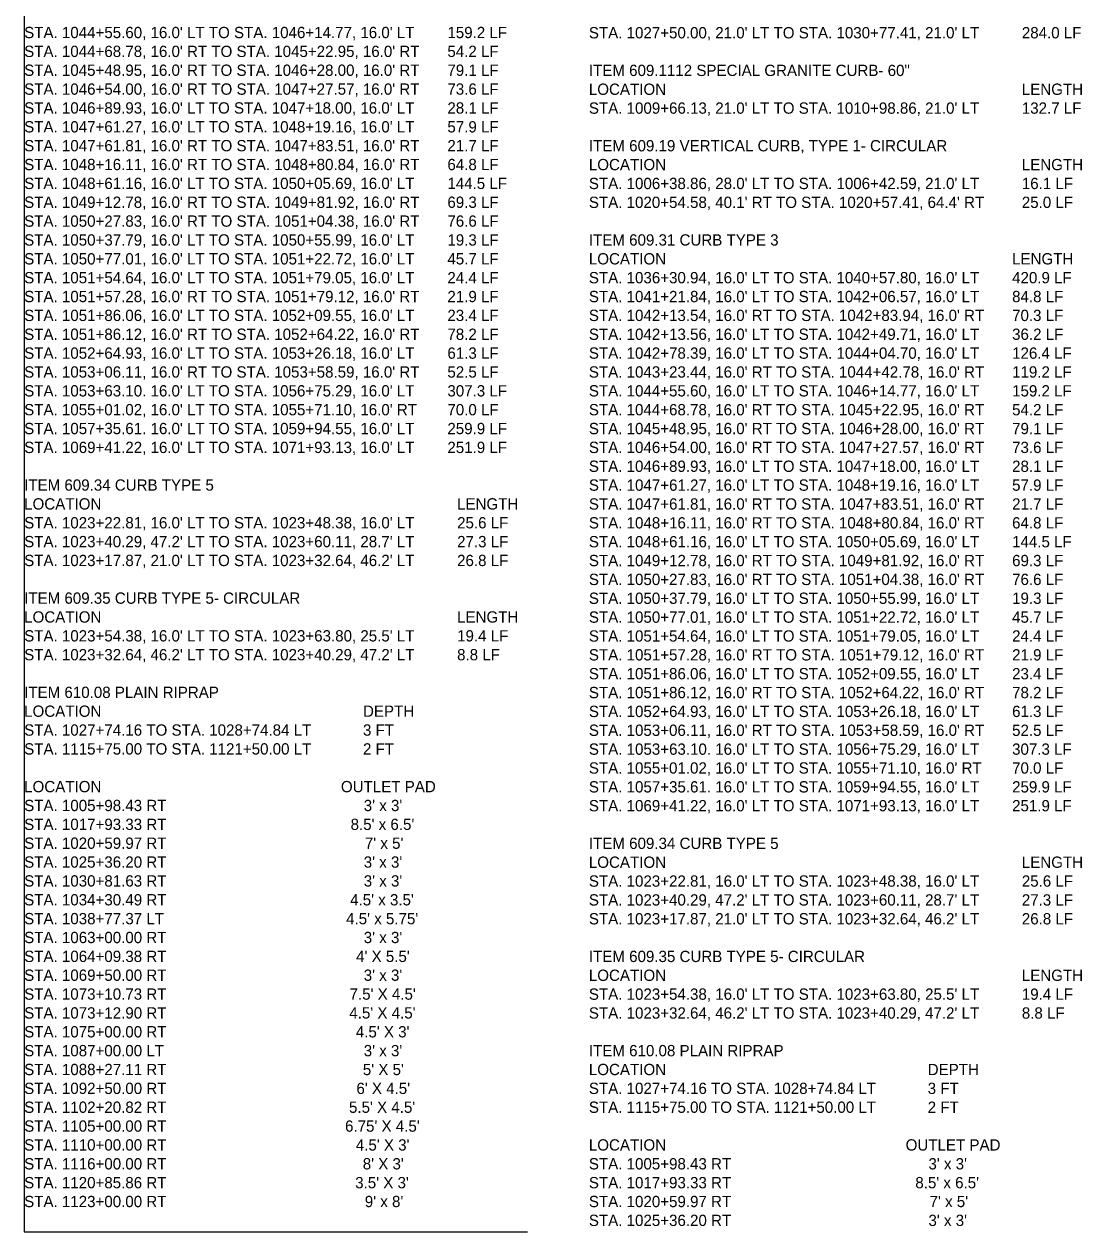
# Model space of a CAD drawing. Extents: x -831 to 3331, y -1004 to 250.
# Drawn here: x -306.8 to -25.8, y -719.8 to -399 of the extents above; entities that cross this region are included whole.
import ezdxf

# ---------------------------------------------------------------- set-up
doc = ezdxf.new("R2010")
doc.units = 0
doc.layers.add('Default', color=7, linetype='Continuous')

msp = doc.modelspace()

# ---------------------------------------------------------------- linework, layer by layer
at = {"layer": 'Default'}
msp.add_line((-306.76, -204.41), (-306.76, -715.41), dxfattribs=at)
msp.add_lwpolyline([(-306.76, -715.41), (-306.76, -719.84), (-173.07, -719.84)], dxfattribs=at)

# ---------------------------------------------------------------- texts
for s, p in [("STA. 1044+55.60, 16.0' LT TO STA. 1046+14.77, 16.0' LT", (-306.76, -402.72)), ('159.2 LF', (-194.34, -402.72)), ("STA. 1027+50.00, 21.0' LT TO STA. 1030+77.41, 21.0' LT", (-156.76, -402.78)), ('284.0 LF', (-41.76, -402.78)), ("STA. 1044+68.78, 16.0' RT TO STA. 1045+22.95, 16.0' RT", (-306.76, -407.73)), ('54.2 LF', (-194.34, -407.73)), ("STA. 1045+48.95, 16.0' RT TO STA. 1046+28.00, 16.0' RT", (-306.76, -412.74)), ('79.1 LF', (-194.34, -412.74)), ('ITEM 609.1112 SPECIAL GRANITE CURB- 60"', (-156.76, -412.78)), ("STA. 1046+54.00, 16.0' RT TO STA. 1047+27.57, 16.0' RT", (-306.76, -417.75)), ('73.6 LF', (-194.34, -417.75)), ('LOCATION', (-156.76, -417.79)), ('LENGTH', (-41.76, -417.79)), ("STA. 1046+89.93, 16.0' LT TO STA. 1047+18.00, 16.0' LT", (-306.76, -422.76)), ('28.1 LF', (-194.34, -422.76)), ("STA. 1009+66.13, 21.0' LT TO STA. 1010+98.86, 21.0' LT", (-156.76, -422.8)), ('132.7 LF', (-41.76, -422.8)), ("STA. 1047+61.27, 16.0' LT TO STA. 1048+19.16, 16.0' LT", (-306.76, -427.77)), ('57.9 LF', (-194.34, -427.77)), ("STA. 1047+61.81, 16.0' RT TO STA. 1047+83.51, 16.0' RT", (-306.76, -432.78)), ('21.7 LF', (-194.34, -432.78)), ('ITEM 609.19 VERTICAL CURB, TYPE 1- CIRCULAR', (-156.76, -432.8)), ("STA. 1048+16.11, 16.0' RT TO STA. 1048+80.84, 16.0' RT", (-306.76, -437.79)), ('64.8 LF', (-194.34, -437.79)), ('LOCATION', (-156.76, -437.81)), ('LENGTH', (-41.76, -437.81)), ("STA. 1048+61.16, 16.0' LT TO STA. 1050+05.69, 16.0' LT", (-306.76, -442.8)), ('144.5 LF', (-194.34, -442.8)), ("STA. 1006+38.86, 28.0' LT TO STA. 1006+42.59, 21.0' LT", (-156.76, -442.82)), ('16.1 LF', (-41.76, -442.82)), ("STA. 1049+12.78, 16.0' RT TO STA. 1049+81.92, 16.0' RT", (-306.76, -447.81)), ('69.3 LF', (-194.34, -447.81)), ("STA. 1020+54.58, 40.1' RT TO STA. 1020+57.41, 64.4' RT", (-156.76, -447.83)), ('25.0 LF', (-41.76, -447.83)), ("STA. 1050+27.83, 16.0' RT TO STA. 1051+04.38, 16.0' RT", (-306.76, -452.82)), ('76.6 LF', (-194.34, -452.82)), ("STA. 1050+37.79, 16.0' LT TO STA. 1050+55.99, 16.0' LT", (-306.76, -457.83)), ('19.3 LF', (-194.34, -457.83)), ('ITEM 609.31 CURB TYPE 3', (-156.76, -457.83)), ("STA. 1050+77.01, 16.0' LT TO STA. 1051+22.72, 16.0' LT", (-306.76, -462.84)), ('45.7 LF', (-194.34, -462.84)), ('LOCATION', (-156.76, -462.84)), ('LENGTH', (-44.34, -462.84)), ("STA. 1051+54.64, 16.0' LT TO STA. 1051+79.05, 16.0' LT", (-306.76, -467.85)), ('24.4 LF', (-194.34, -467.85)), ("STA. 1036+30.94, 16.0' LT TO STA. 1040+57.80, 16.0' LT", (-156.76, -467.85)), ('420.9 LF', (-44.34, -467.85)), ("STA. 1051+57.28, 16.0' RT TO STA. 1051+79.12, 16.0' RT", (-306.76, -472.86)), ('21.9 LF', (-194.34, -472.86)), ("STA. 1041+21.84, 16.0' LT TO STA. 1042+06.57, 16.0' LT", (-156.76, -472.86)), ('84.8 LF', (-44.34, -472.86)), ("STA. 1051+86.06, 16.0' LT TO STA. 1052+09.55, 16.0' LT", (-306.76, -477.87)), ('23.4 LF', (-194.34, -477.87)), ("STA. 1042+13.54, 16.0' RT TO STA. 1042+83.94, 16.0' RT", (-156.76, -477.87)), ('70.3 LF', (-44.34, -477.87)), ("STA. 1051+86.12, 16.0' RT TO STA. 1052+64.22, 16.0' RT", (-306.76, -482.88)), ('78.2 LF', (-194.34, -482.88)), ("STA. 1042+13.56, 16.0' LT TO STA. 1042+49.71, 16.0' LT", (-156.76, -482.88)), ('36.2 LF', (-44.34, -482.88)), ("STA. 1052+64.93, 16.0' LT TO STA. 1053+26.18, 16.0' LT", (-306.76, -487.89)), ('61.3 LF', (-194.34, -487.89)), ("STA. 1042+78.39, 16.0' LT TO STA. 1044+04.70, 16.0' LT", (-156.76, -487.89)), ('126.4 LF', (-44.34, -487.89)), ("STA. 1053+06.11, 16.0' RT TO STA. 1053+58.59, 16.0' RT", (-306.76, -492.9)), ('52.5 LF', (-194.34, -492.9)), ("STA. 1043+23.44, 16.0' RT TO STA. 1044+42.78, 16.0' RT", (-156.76, -492.9)), ('119.2 LF', (-44.34, -492.9)), ("STA. 1053+63.10. 16.0' LT TO STA. 1056+75.29, 16.0' LT", (-306.76, -497.91)), ('307.3 LF', (-194.34, -497.91)), ("STA. 1044+55.60, 16.0' LT TO STA. 1046+14.77, 16.0' LT", (-156.76, -497.91)), ('159.2 LF', (-44.34, -497.91)), ("STA. 1055+01.02, 16.0' LT TO STA. 1055+71.10, 16.0' RT", (-306.76, -502.92)), ('70.0 LF', (-194.34, -502.92)), ("STA. 1044+68.78, 16.0' RT TO STA. 1045+22.95, 16.0' RT", (-156.76, -502.92)), ('54.2 LF', (-44.34, -502.92)), ("STA. 1057+35.61. 16.0' LT TO STA. 1059+94.55, 16.0' LT", (-306.76, -507.93)), ('259.9 LF', (-194.34, -507.93)), ("STA. 1045+48.95, 16.0' RT TO STA. 1046+28.00, 16.0' RT", (-156.76, -507.93)), ('79.1 LF', (-44.34, -507.93)), ("STA. 1069+41.22, 16.0' LT TO STA. 1071+93.13, 16.0' LT", (-306.76, -512.94)), ('251.9 LF', (-194.34, -512.94)), ("STA. 1046+54.00, 16.0' RT TO STA. 1047+27.57, 16.0' RT", (-156.76, -512.94)), ('73.6 LF', (-44.34, -512.94)), ("STA. 1046+89.93, 16.0' LT TO STA. 1047+18.00, 16.0' LT", (-156.76, -517.95)), ('28.1 LF', (-44.34, -517.95)), ('ITEM 609.34 CURB TYPE 5', (-306.76, -522.94)), ("STA. 1047+61.27, 16.0' LT TO STA. 1048+19.16, 16.0' LT", (-156.76, -522.96)), ('57.9 LF', (-44.34, -522.96)), ('LOCATION', (-306.76, -527.95)), ('LENGTH', (-191.76, -527.95)), ("STA. 1047+61.81, 16.0' RT TO STA. 1047+83.51, 16.0' RT", (-156.76, -527.97)), ('21.7 LF', (-44.34, -527.97)), ("STA. 1023+22.81, 16.0' LT TO STA. 1023+48.38, 16.0' LT", (-306.76, -532.96)), ('25.6 LF', (-191.76, -532.96)), ("STA. 1048+16.11, 16.0' RT TO STA. 1048+80.84, 16.0' RT", (-156.76, -532.98)), ('64.8 LF', (-44.34, -532.98)), ("STA. 1023+40.29, 47.2' LT TO STA. 1023+60.11, 28.7' LT", (-306.76, -537.97)), ('27.3 LF', (-191.76, -537.97)), ("STA. 1048+61.16, 16.0' LT TO STA. 1050+05.69, 16.0' LT", (-156.76, -537.99)), ('144.5 LF', (-44.34, -537.99)), ("STA. 1023+17.87, 21.0' LT TO STA. 1023+32.64, 46.2' LT", (-306.76, -542.98)), ('26.8 LF', (-191.76, -542.98)), ("STA. 1049+12.78, 16.0' RT TO STA. 1049+81.92, 16.0' RT", (-156.76, -543)), ('69.3 LF', (-44.34, -543)), ("STA. 1050+27.83, 16.0' RT TO STA. 1051+04.38, 16.0' RT", (-156.76, -548.01)), ('76.6 LF', (-44.34, -548.01)), ('ITEM 609.35 CURB TYPE 5- CIRCULAR', (-306.76, -552.98)), ("STA. 1050+37.79, 16.0' LT TO STA. 1050+55.99, 16.0' LT", (-156.76, -553.02)), ('19.3 LF', (-44.34, -553.02)), ('LOCATION', (-306.76, -557.99)), ('LENGTH', (-191.76, -557.99)), ("STA. 1050+77.01, 16.0' LT TO STA. 1051+22.72, 16.0' LT", (-156.76, -558.03)), ('45.7 LF', (-44.34, -558.03)), ("STA. 1023+54.38, 16.0' LT TO STA. 1023+63.80, 25.5' LT", (-306.76, -563)), ('19.4 LF', (-191.76, -563)), ("STA. 1051+54.64, 16.0' LT TO STA. 1051+79.05, 16.0' LT", (-156.76, -563.04)), ('24.4 LF', (-44.34, -563.04)), ("STA. 1023+32.64, 46.2' LT TO STA. 1023+40.29, 47.2' LT", (-306.76, -568.01)), ('8.8 LF', (-191.76, -568.01)), ("STA. 1051+57.28, 16.0' RT TO STA. 1051+79.12, 16.0' RT", (-156.76, -568.05)), ('21.9 LF', (-44.34, -568.05)), ("STA. 1051+86.06, 16.0' LT TO STA. 1052+09.55, 16.0' LT", (-156.76, -573.06)), ('23.4 LF', (-44.34, -573.06)), ('ITEM 610.08 PLAIN RIPRAP', (-306.76, -578.01)), ("STA. 1051+86.12, 16.0' RT TO STA. 1052+64.22, 16.0' RT", (-156.76, -578.07)), ('78.2 LF', (-44.34, -578.07)), ('LOCATION', (-306.76, -583.02)), ('DEPTH', (-216.76, -583.02)), ("STA. 1052+64.93, 16.0' LT TO STA. 1053+26.18, 16.0' LT", (-156.76, -583.08)), ('61.3 LF', (-44.34, -583.08)), ('STA. 1027+74.16 TO STA. 1028+74.84 LT', (-306.76, -588.03)), ('3 FT', (-216.76, -588.03)), ("STA. 1053+06.11, 16.0' RT TO STA. 1053+58.59, 16.0' RT", (-156.76, -588.09)), ('52.5 LF', (-44.34, -588.09)), ('STA. 1115+75.00 TO STA. 1121+50.00 LT', (-306.76, -593.04)), ('2 FT', (-216.76, -593.04)), ("STA. 1053+63.10. 16.0' LT TO STA. 1056+75.29, 16.0' LT", (-156.76, -593.1)), ('307.3 LF', (-44.34, -593.1)), ("STA. 1055+01.02, 16.0' LT TO STA. 1055+71.10, 16.0' RT", (-156.76, -598.11)), ('70.0 LF', (-44.34, -598.11)), ('LOCATION', (-306.76, -603.06)), ('OUTLET PAD', (-222.62, -603.06)), ("STA. 1057+35.61. 16.0' LT TO STA. 1059+94.55, 16.0' LT", (-156.76, -603.12)), ('259.9 LF', (-44.34, -603.12)), ('STA. 1005+98.43 RT', (-306.76, -608.07)), ("3' x 3'", (-216.56, -608.07)), ("STA. 1069+41.22, 16.0' LT TO STA. 1071+93.13, 16.0' LT", (-156.76, -608.13)), ('251.9 LF', (-44.34, -608.13)), ('STA. 1017+93.33 RT', (-306.76, -613.08)), ("8.5' x 6.5'", (-220.05, -613.08)), ('STA. 1020+59.97 RT', (-306.76, -618.09)), ("7' x 5'", (-216.26, -618.09)), ('ITEM 609.34 CURB TYPE 5', (-156.76, -618.13)), ('STA. 1025+36.20 RT', (-306.76, -623.1)), ("3' x 3'", (-216.56, -623.1)), ('LOCATION', (-156.76, -623.14)), ('LENGTH', (-41.76, -623.14)), ('STA. 1030+81.63 RT', (-306.76, -628.11)), ("3' x 3'", (-216.56, -628.11)), ("STA. 1023+22.81, 16.0' LT TO STA. 1023+48.38, 16.0' LT", (-156.76, -628.15)), ('25.6 LF', (-41.76, -628.15)), ('STA. 1034+30.49 RT', (-306.76, -633.12)), ("4.5' x 3.5'", (-220.17, -633.12)), ("STA. 1023+40.29, 47.2' LT TO STA. 1023+60.11, 28.7' LT", (-156.76, -633.16)), ('27.3 LF', (-41.76, -633.16)), ('STA. 1038+77.37 LT', (-306.76, -638.13)), ("4.5' x 5.75'", (-221.24, -638.13)), ("STA. 1023+17.87, 21.0' LT TO STA. 1023+32.64, 46.2' LT", (-156.76, -638.17)), ('26.8 LF', (-41.76, -638.17)), ('STA. 1063+00.00 RT', (-306.76, -643.14)), ("3' x 3'", (-216.56, -643.14)), ('STA. 1064+09.38 RT', (-306.76, -648.15)), ("4' X 5.5'", (-218.59, -648.15)), ('ITEM 609.35 CURB TYPE 5- CIRCULAR', (-156.76, -648.17)), ('STA. 1069+50.00 RT', (-306.76, -653.16)), ("3' x 3'", (-216.56, -653.16)), ('LOCATION', (-156.76, -653.18)), ('LENGTH', (-41.76, -653.18)), ('STA. 1073+10.73 RT', (-306.76, -658.17)), ("7.5' X 4.5'", (-220.32, -658.17)), ("STA. 1023+54.38, 16.0' LT TO STA. 1023+63.80, 25.5' LT", (-156.76, -658.19)), ('19.4 LF', (-41.76, -658.19)), ('STA. 1073+12.90 RT', (-306.76, -663.18)), ("4.5' X 4.5'", (-220.39, -663.18)), ("STA. 1023+32.64, 46.2' LT TO STA. 1023+40.29, 47.2' LT", (-156.76, -663.2)), ('8.8 LF', (-41.76, -663.2)), ('STA. 1075+00.00 RT', (-306.76, -668.19)), ("4.5' X 3'", (-218.66, -668.19)), ('STA. 1087+00.00 LT', (-306.76, -673.2)), ("3' x 3'", (-216.56, -673.2)), ('ITEM 610.08 PLAIN RIPRAP', (-156.76, -673.2)), ('STA. 1088+27.11 RT', (-306.76, -678.21)), ("5' X 5'", (-216.8, -678.21)), ('LOCATION', (-156.76, -678.21)), ('DEPTH', (-66.76, -678.21)), ('STA. 1092+50.00 RT', (-306.76, -683.22)), ("6' X 4.5'", (-218.5, -683.22)), ('STA. 1027+74.16 TO STA. 1028+74.84 LT', (-156.76, -683.22)), ('3 FT', (-66.76, -683.22)), ('STA. 1102+20.82 RT', (-306.76, -688.23)), ("5.5' X 4.5'", (-220.48, -688.23)), ('STA. 1115+75.00 TO STA. 1121+50.00 LT', (-156.76, -688.23)), ('2 FT', (-66.76, -688.23)), ('STA. 1105+00.00 RT', (-306.76, -693.24)), ("6.75' X 4.5'", (-221.52, -693.24)), ('STA. 1110+00.00 RT', (-306.76, -698.25)), ("4.5' X 3'", (-218.66, -698.25)), ('LOCATION', (-156.76, -698.25)), ('OUTLET PAD', (-72.62, -698.25)), ('STA. 1116+00.00 RT', (-306.76, -703.26)), ("8' X 3'", (-216.82, -703.26)), ('STA. 1005+98.43 RT', (-156.76, -703.26)), ("3' x 3'", (-66.56, -703.26)), ('STA. 1120+85.86 RT', (-306.76, -708.27)), ("3.5' X 3'", (-218.83, -708.27)), ('STA. 1017+93.33 RT', (-156.76, -708.27)), ("8.5' x 6.5'", (-70.05, -708.27)), ('STA. 1123+00.00 RT', (-306.76, -713.28)), ("9' x 8'", (-216.28, -713.28)), ('STA. 1020+59.97 RT', (-156.76, -713.28)), ("7' x 5'", (-66.26, -713.28)), ('STA. 1025+36.20 RT', (-156.76, -718.29)), ("3' x 3'", (-66.56, -718.29))]:
    msp.add_text(s, height=3, dxfattribs=at).set_placement(p)

doc.saveas('drawing.dxf')
